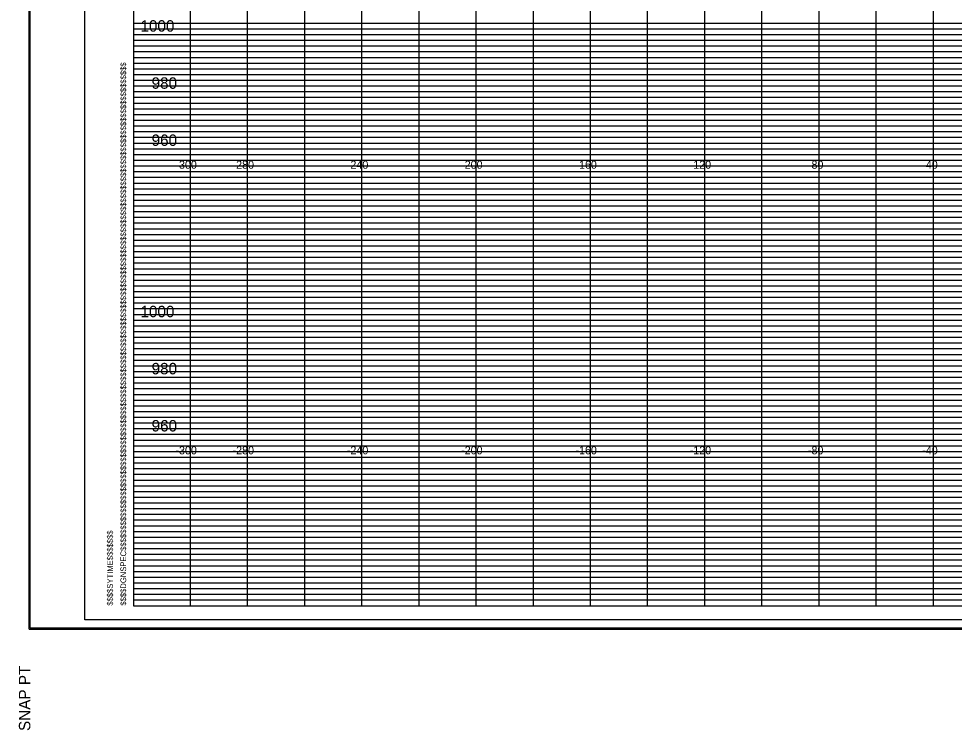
# Model space of a CAD drawing. Extents: x 2313580 to 2322968, y 282099 to 303247.
# Drawn here: x 2317632.4 to 2317959.8, y 287544 to 287793.2 of the extents above; entities that cross this region are included whole.
import ezdxf

# ---------------------------------------------------------------- set-up
doc = ezdxf.new("R2010")
doc.units = 0
for name, color, linetype in [('DESIGN - SHEET - Corner Text', 7, 'Continuous'), ('DESIGN - SHEET - Light Grid', 7, 'Continuous'), ('DESIGN - SHEET - Linework', 7, 'Continuous'), ('DESIGN - SHEET - Plot Shape', 7, 'Continuous'), ('DESIGN - TYPICAL - Text', 7, 'Continuous')]:
    doc.layers.add(name, color=color, linetype=linetype)

msp = doc.modelspace()

# ---------------------------------------------------------------- linework, layer by layer
at = {"layer": 'DESIGN - SHEET - Light Grid'}
for p, q in [((2317672.48, 287791.67), (2317832.48, 287791.67)), ((2317832.48, 287791.67), (2317992.48, 287791.67)), ((2317672.48, 287789.67), (2317832.48, 287789.67)), ((2317832.48, 287789.67), (2317992.48, 287789.67)), ((2317672.48, 287785.67), (2317832.48, 287785.67)), ((2317832.48, 287785.67), (2317992.48, 287785.67)), ((2317672.48, 287783.67), (2317832.48, 287783.67)), ((2317672.48, 287781.67), (2317832.48, 287781.67)), ((2317832.48, 287783.67), (2317992.48, 287783.67)), ((2317832.48, 287781.67), (2317992.48, 287781.67)), ((2317672.48, 287779.67), (2317832.48, 287779.67)), ((2317672.48, 287777.67), (2317832.48, 287777.67)), ((2317832.48, 287779.67), (2317992.48, 287779.67)), ((2317832.48, 287777.67), (2317992.48, 287777.67)), ((2317672.48, 287775.67), (2317832.48, 287775.67)), ((2317832.48, 287775.67), (2317992.48, 287775.67)), ((2317672.48, 287773.67), (2317832.48, 287773.67)), ((2317672.48, 287771.67), (2317832.48, 287771.67)), ((2317832.48, 287773.67), (2317992.48, 287773.67)), ((2317832.48, 287771.67), (2317992.48, 287771.67)), ((2317672.48, 287769.67), (2317832.48, 287769.67)), ((2317832.48, 287769.67), (2317992.48, 287769.67)), ((2317672.48, 287765.67), (2317832.48, 287765.67)), ((2317832.48, 287765.67), (2317992.48, 287765.67)), ((2317672.48, 287763.67), (2317832.48, 287763.67)), ((2317672.48, 287761.67), (2317832.48, 287761.67)), ((2317832.48, 287763.67), (2317992.48, 287763.67)), ((2317832.48, 287761.67), (2317992.48, 287761.67)), ((2317672.48, 287759.67), (2317832.48, 287759.67)), ((2317832.48, 287759.67), (2317992.48, 287759.67)), ((2317672.48, 287757.67), (2317832.48, 287757.67)), ((2317672.48, 287755.67), (2317832.48, 287755.67)), ((2317832.48, 287757.67), (2317992.48, 287757.67)), ((2317832.48, 287755.67), (2317992.48, 287755.67)), ((2317672.48, 287753.67), (2317832.48, 287753.67)), ((2317672.48, 287751.67), (2317832.48, 287751.67)), ((2317832.48, 287753.67), (2317992.48, 287753.67)), ((2317832.48, 287751.67), (2317992.48, 287751.67)), ((2317672.48, 287749.67), (2317832.48, 287749.67)), ((2317832.48, 287749.67), (2317992.48, 287749.67)), ((2317672.48, 287745.67), (2317832.48, 287745.67)), ((2317832.48, 287745.67), (2317992.48, 287745.67)), ((2317672.48, 287743.67), (2317832.48, 287743.67)), ((2317672.48, 287741.67), (2317832.48, 287741.67)), ((2317832.48, 287743.67), (2317992.48, 287743.67)), ((2317832.48, 287741.67), (2317992.48, 287741.67)), ((2317672.48, 287739.67), (2317832.48, 287739.67)), ((2317832.48, 287739.67), (2317992.48, 287739.67)), ((2317672.48, 287737.67), (2317832.48, 287737.67)), ((2317672.48, 287735.67), (2317832.48, 287735.67)), ((2317832.48, 287737.67), (2317992.48, 287737.67)), ((2317832.48, 287735.67), (2317992.48, 287735.67)), ((2317672.48, 287733.67), (2317832.48, 287733.67)), ((2317672.48, 287731.67), (2317832.48, 287731.67)), ((2317832.48, 287733.67), (2317992.48, 287733.67)), ((2317832.48, 287731.67), (2317992.48, 287731.67)), ((2317672.48, 287729.67), (2317832.48, 287729.67)), ((2317832.48, 287729.67), (2317992.48, 287729.67)), ((2317672.48, 287725.67), (2317832.48, 287725.67)), ((2317832.48, 287725.67), (2317992.48, 287725.67)), ((2317672.48, 287723.67), (2317832.48, 287723.67)), ((2317832.48, 287723.67), (2317992.48, 287723.67)), ((2317672.48, 287721.67), (2317832.48, 287721.67)), ((2317672.48, 287719.67), (2317832.48, 287719.67)), ((2317832.48, 287721.67), (2317992.48, 287721.67)), ((2317832.48, 287719.67), (2317992.48, 287719.67)), ((2317672.48, 287717.67), (2317832.48, 287717.67)), ((2317672.48, 287715.67), (2317832.48, 287715.67)), ((2317832.48, 287717.67), (2317992.48, 287717.67)), ((2317832.48, 287715.67), (2317992.48, 287715.67)), ((2317672.48, 287713.67), (2317832.48, 287713.67)), ((2317832.48, 287713.67), (2317992.48, 287713.67)), ((2317672.48, 287711.67), (2317832.48, 287711.67)), ((2317672.48, 287709.67), (2317832.48, 287709.67)), ((2317832.48, 287711.67), (2317992.48, 287711.67)), ((2317832.48, 287709.67), (2317992.48, 287709.67)), ((2317672.48, 287705.67), (2317832.48, 287705.67)), ((2317832.48, 287705.67), (2317992.48, 287705.67)), ((2317672.48, 287703.67), (2317832.48, 287703.67)), ((2317832.48, 287703.67), (2317992.48, 287703.67)), ((2317672.48, 287701.67), (2317832.48, 287701.67)), ((2317672.48, 287699.67), (2317832.48, 287699.67)), ((2317832.48, 287701.67), (2317992.48, 287701.67)), ((2317832.48, 287699.67), (2317992.48, 287699.67)), ((2317672.48, 287697.67), (2317832.48, 287697.67)), ((2317672.48, 287695.67), (2317832.48, 287695.67)), ((2317832.48, 287697.67), (2317992.48, 287697.67)), ((2317832.48, 287695.67), (2317992.48, 287695.67)), ((2317672.48, 287693.67), (2317832.48, 287693.67)), ((2317832.48, 287693.67), (2317992.48, 287693.67)), ((2317672.48, 287691.67), (2317832.48, 287691.67)), ((2317672.48, 287689.67), (2317832.48, 287689.67)), ((2317832.48, 287691.67), (2317992.48, 287691.67)), ((2317832.48, 287689.67), (2317992.48, 287689.67)), ((2317672.48, 287685.67), (2317832.48, 287685.67)), ((2317672.48, 287683.67), (2317832.48, 287683.67)), ((2317832.48, 287685.67), (2317992.48, 287685.67)), ((2317832.48, 287683.67), (2317992.48, 287683.67)), ((2317672.48, 287681.67), (2317832.48, 287681.67)), ((2317672.48, 287679.67), (2317832.48, 287679.67)), ((2317832.48, 287681.67), (2317992.48, 287681.67)), ((2317832.48, 287679.67), (2317992.48, 287679.67)), ((2317672.48, 287677.67), (2317832.48, 287677.67)), ((2317832.48, 287677.67), (2317992.48, 287677.67)), ((2317672.48, 287675.67), (2317832.48, 287675.67)), ((2317672.48, 287673.67), (2317832.48, 287673.67)), ((2317832.48, 287675.67), (2317992.48, 287675.67)), ((2317832.48, 287673.67), (2317992.48, 287673.67)), ((2317672.48, 287671.67), (2317832.48, 287671.67)), ((2317672.48, 287669.67), (2317832.48, 287669.67)), ((2317832.48, 287671.67), (2317992.48, 287671.67)), ((2317832.48, 287669.67), (2317992.48, 287669.67)), ((2317672.48, 287665.67), (2317832.48, 287665.67)), ((2317672.48, 287663.67), (2317832.48, 287663.67)), ((2317832.48, 287665.67), (2317992.48, 287665.67)), ((2317832.48, 287663.67), (2317992.48, 287663.67)), ((2317672.48, 287661.67), (2317832.48, 287661.67)), ((2317672.48, 287659.67), (2317832.48, 287659.67)), ((2317832.48, 287661.67), (2317992.48, 287661.67)), ((2317832.48, 287659.67), (2317992.48, 287659.67)), ((2317672.48, 287657.67), (2317832.48, 287657.67)), ((2317832.48, 287657.67), (2317992.48, 287657.67)), ((2317672.48, 287655.67), (2317832.48, 287655.67)), ((2317672.48, 287653.67), (2317832.48, 287653.67)), ((2317832.48, 287655.67), (2317992.48, 287655.67)), ((2317832.48, 287653.67), (2317992.48, 287653.67)), ((2317672.48, 287651.67), (2317832.48, 287651.67)), ((2317832.48, 287651.67), (2317992.48, 287651.67)), ((2317672.48, 287649.67), (2317832.48, 287649.67)), ((2317832.48, 287649.67), (2317992.48, 287649.67)), ((2317672.48, 287645.67), (2317832.48, 287645.67)), ((2317672.48, 287643.67), (2317832.48, 287643.67)), ((2317832.48, 287645.67), (2317992.48, 287645.67)), ((2317832.48, 287643.67), (2317992.48, 287643.67)), ((2317672.48, 287641.67), (2317832.48, 287641.67)), ((2317832.48, 287641.67), (2317992.48, 287641.67)), ((2317672.48, 287639.67), (2317832.48, 287639.67)), ((2317672.48, 287637.67), (2317832.48, 287637.67)), ((2317832.48, 287639.67), (2317992.48, 287639.67)), ((2317832.48, 287637.67), (2317992.48, 287637.67)), ((2317672.48, 287635.67), (2317832.48, 287635.67)), ((2317672.48, 287633.67), (2317832.48, 287633.67)), ((2317832.48, 287635.67), (2317992.48, 287635.67)), ((2317832.48, 287633.67), (2317992.48, 287633.67)), ((2317672.48, 287631.67), (2317832.48, 287631.67)), ((2317832.48, 287631.67), (2317992.48, 287631.67)), ((2317672.48, 287629.67), (2317832.48, 287629.67)), ((2317832.48, 287629.67), (2317992.48, 287629.67)), ((2317672.48, 287625.67), (2317832.48, 287625.67)), ((2317672.48, 287623.67), (2317832.48, 287623.67)), ((2317832.48, 287625.67), (2317992.48, 287625.67)), ((2317832.48, 287623.67), (2317992.48, 287623.67)), ((2317672.48, 287621.67), (2317832.48, 287621.67)), ((2317832.48, 287621.67), (2317992.48, 287621.67)), ((2317672.48, 287619.67), (2317832.48, 287619.67)), ((2317672.48, 287617.67), (2317832.48, 287617.67)), ((2317832.48, 287619.67), (2317992.48, 287619.67)), ((2317832.48, 287617.67), (2317992.48, 287617.67)), ((2317672.48, 287615.67), (2317832.48, 287615.67)), ((2317672.48, 287613.67), (2317832.48, 287613.67)), ((2317832.48, 287615.67), (2317992.48, 287615.67)), ((2317832.48, 287613.67), (2317992.48, 287613.67)), ((2317672.48, 287611.67), (2317832.48, 287611.67)), ((2317832.48, 287611.67), (2317992.48, 287611.67)), ((2317672.48, 287609.67), (2317832.48, 287609.67)), ((2317832.48, 287609.67), (2317992.48, 287609.67)), ((2317672.48, 287605.67), (2317832.48, 287605.67)), ((2317832.48, 287605.67), (2317992.48, 287605.67)), ((2317672.48, 287603.67), (2317832.48, 287603.67)), ((2317672.48, 287601.67), (2317832.48, 287601.67)), ((2317832.48, 287603.67), (2317992.48, 287603.67)), ((2317832.48, 287601.67), (2317992.48, 287601.67)), ((2317672.48, 287599.67), (2317832.48, 287599.67)), ((2317672.48, 287597.67), (2317832.48, 287597.67)), ((2317832.48, 287599.67), (2317992.48, 287599.67)), ((2317832.48, 287597.67), (2317992.48, 287597.67)), ((2317672.48, 287595.67), (2317832.48, 287595.67)), ((2317832.48, 287595.67), (2317992.48, 287595.67)), ((2317672.48, 287593.67), (2317832.48, 287593.67)), ((2317672.48, 287591.67), (2317832.48, 287591.67)), ((2317832.48, 287593.67), (2317992.48, 287593.67)), ((2317832.48, 287591.67), (2317992.48, 287591.67)), ((2317672.48, 287589.67), (2317832.48, 287589.67)), ((2317832.48, 287589.67), (2317992.48, 287589.67))]:
    msp.add_line(p, q, dxfattribs=at)
at = {"layer": 'DESIGN - SHEET - Linework'}
for p, q in [((2317636.02, 287579.39), (2317636.02, 288015.95)), ((2317692.48, 287587.67), (2317692.48, 288007.67)), ((2317712.48, 287587.67), (2317712.48, 288007.67)), ((2317732.48, 287587.67), (2317732.48, 288007.67)), ((2317752.48, 287587.67), (2317752.48, 288007.67)), ((2317772.48, 287587.67), (2317772.48, 288007.67)), ((2317792.48, 287587.67), (2317792.48, 288007.67)), ((2317812.48, 287587.67), (2317812.48, 288007.67)), ((2317832.48, 287587.67), (2317832.48, 288007.67)), ((2317852.48, 287587.67), (2317852.48, 288007.67)), ((2317872.48, 287587.67), (2317872.48, 288007.67)), ((2317892.48, 287587.67), (2317892.48, 288007.67)), ((2317912.48, 287587.67), (2317912.48, 288007.67)), ((2317932.48, 287587.67), (2317932.48, 288007.67)), ((2317952.48, 287587.67), (2317952.48, 288007.67)), ((2317672.48, 287787.67), (2318312.48, 287787.67)), ((2317672.48, 287767.67), (2318312.48, 287767.67)), ((2317672.48, 287747.67), (2318312.48, 287747.67)), ((2317672.48, 287727.67), (2318312.48, 287727.67)), ((2317672.48, 287707.67), (2318312.48, 287707.67)), ((2317672.48, 287687.67), (2318312.48, 287687.67)), ((2317672.48, 287667.67), (2318312.48, 287667.67)), ((2317672.48, 287647.67), (2318312.48, 287647.67)), ((2317672.48, 287627.67), (2318312.48, 287627.67)), ((2317672.48, 287607.67), (2318312.48, 287607.67)), ((2317636.02, 287579.39), (2318316.82, 287579.39))]:
    msp.add_line(p, q, dxfattribs=at)
msp.add_lwpolyline([(2317672.48, 288007.67), (2317672.48, 287587.67), (2318312.48, 287587.67), (2318312.48, 288007.67), (2317672.48, 288007.67)], dxfattribs=at)
at = {"layer": 'DESIGN - SHEET - Plot Shape'}
for points in [[(2317636.42, 288015.55), (2318316.42, 288015.55), (2318316.42, 287579.79), (2317636.42, 287579.79)], [(2317655.48, 288007.67), (2318312.48, 288007.67), (2318312.48, 287582.67), (2317655.48, 287582.67)]]:
    msp.add_lwpolyline(points, close=True, dxfattribs=at)

# ---------------------------------------------------------------- texts
at = {"layer": 'DESIGN - SHEET - Corner Text'}
for s, height, p in [('$$$$DGNSPEC$$$$$$$$$$$$$$$$$$$$$$$$$$$$$$$$$$$$$$$$$$$$$$$$$$$$$$$$$$$$$$$$$$$$$$$$$$$$$$$$$$$$$$$$$$$$$$$$$$$$$$$$$$$$$$$$$$$', 2.00004, (2317669.96, 287587.67)), ('$$$$SYTIME$$$$$$$', 2, (2317665.32, 287587.67)), ('SNAP PT  ', 4, (2317636.42, 287543.79))]:
    msp.add_text(s, height=height, rotation=90, dxfattribs=at).set_placement(p)
at = {"layer": 'DESIGN - SHEET - Linework'}
for p in [(2317692.48, 287747.67), (2317692.48, 287647.67)]:
    msp.add_text('-', height=0.0001, dxfattribs=at).set_placement(p)
at = {"layer": 'DESIGN - TYPICAL - Text'}
for s, height, p in [('1000', 4, (2317674.96, 287788.67)), ('980', 4, (2317678.86, 287768.67)), ('960', 4, (2317678.86, 287748.67)), ('-300', 2.8, (2317687.22, 287740.67)), ('-280', 2.8, (2317707.22, 287740.67)), ('-240', 2.8, (2317747.22, 287740.67)), ('-200', 2.8, (2317787.22, 287740.67)), ('-160', 2.8, (2317827.22, 287740.67)), ('-120', 2.8, (2317867.22, 287740.67)), ('-80', 2.8, (2317908.59, 287740.67)), ('-40', 2.8, (2317948.59, 287740.67)), ('1000', 4, (2317674.96, 287688.67)), ('980', 4, (2317678.86, 287668.67)), ('960', 4, (2317678.86, 287648.67)), ('-300', 2.8, (2317687.22, 287640.67)), ('-280', 2.8, (2317707.22, 287640.67)), ('-240', 2.8, (2317747.22, 287640.67)), ('-200', 2.8, (2317787.22, 287640.67)), ('-160', 2.8, (2317827.22, 287640.67)), ('-120', 2.8, (2317867.22, 287640.67)), ('-80', 2.8, (2317908.59, 287640.67)), ('-40', 2.8, (2317948.59, 287640.67))]:
    msp.add_text(s, height=height, dxfattribs=at).set_placement(p)

doc.saveas('drawing.dxf')
